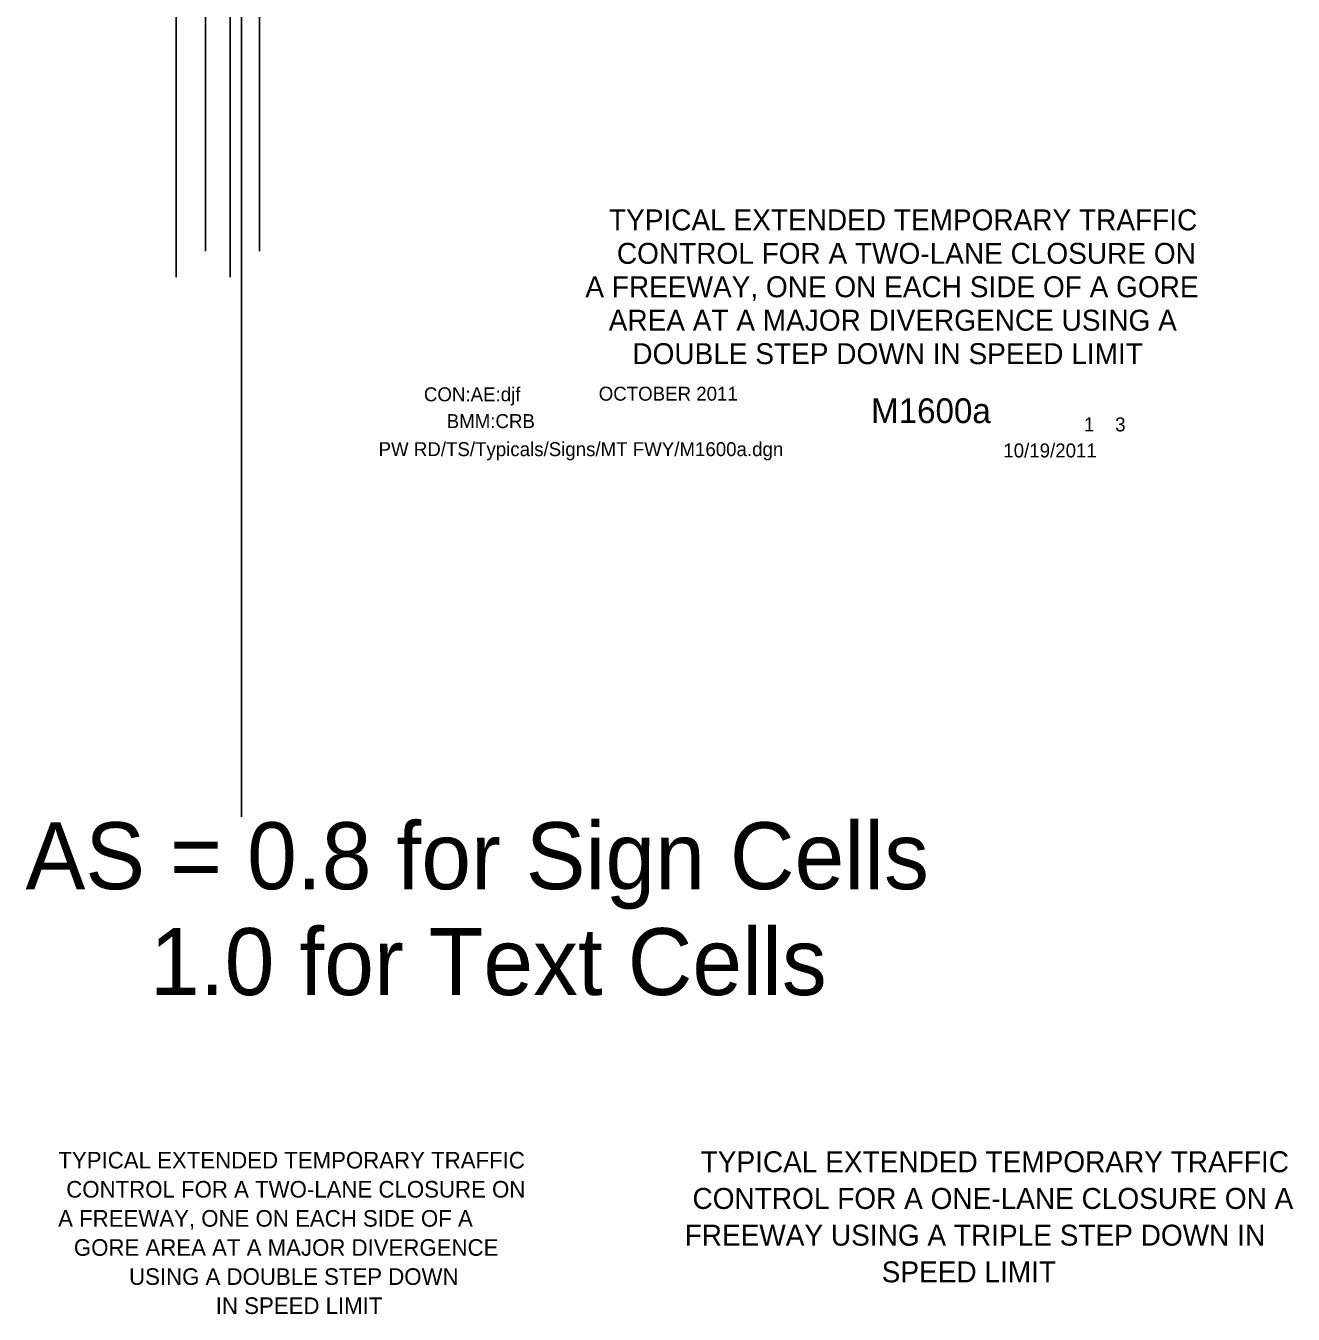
# Model space of a CAD drawing. Extents: x 16728 to 19508, y 5553 to 7079.
# Drawn here: x 16914 to 17477, y 5553 to 6125 of the extents above; entities that cross this region are included whole.
import ezdxf

# ---------------------------------------------------------------- set-up
doc = ezdxf.new("R2010")
doc.units = 0
for name, color, linetype in [('ALI_LEGAL_EX', 7, 'Continuous'), ('BORDER', 7, 'Continuous'), ('BORDER_SIGNAL_WO', 7, 'Continuous')]:
    doc.layers.add(name, color=color, linetype=linetype)

msp = doc.modelspace()

# ---------------------------------------------------------------- linework, layer by layer
at = {"layer": 'ALI_LEGAL_EX'}
for p, q in [((16980.68, 6877.04), (16980.68, 6013.12)), ((17004.68, 6877.04), (17004.68, 6013.12)), ((16993.65, 6024.8), (16993.65, 6525.15)), ((17017.65, 6024.8), (17017.65, 6525.15)), ((17009.75, 5773.57), (17009.75, 6383.76))]:
    msp.add_line(p, q, dxfattribs=at)
msp.add_lwpolyline([(16993.65, 6049.8), (16993.65, 6024.8)], dxfattribs=at)

# ---------------------------------------------------------------- texts
at = {"layer": 'BORDER'}
for s, height, p in [('TYPICAL EXTENDED TEMPORARY TRAFFIC', 9.3, (17172.85, 6033.97)), ('CONTROL FOR A TWO-LANE CLOSURE ON', 9.3, (17176.35, 6019.11)), ('A FREEWAY, ONE ON EACH SIDE OF A GORE', 9.3, (17162.37, 6004.27)), ('AREA AT A MAJOR DIVERGENCE USING A', 9.3, (17172.72, 5989.41)), ('DOUBLE STEP DOWN IN SPEED LIMIT', 9.3, (17183.22, 5974.57)), ('TYPICAL EXTENDED TEMPORARY TRAFFIC', 7.3743, (16928.4, 5617.4)), ('TYPICAL EXTENDED TEMPORARY TRAFFIC', 9.3, (17213.56, 5615.73)), ('CONTROL FOR A TWO-LANE CLOSURE ON', 7.3743, (16931.9, 5604.47)), ('CONTROL FOR A ONE-LANE CLOSURE ON A', 9.3, (17209.93, 5599.43)), ('A FREEWAY, ONE ON EACH SIDE OF A  ', 7.3743, (16928.28, 5591.55)), ('FREEWAY USING A TRIPLE STEP DOWN IN ', 9.3, (17206.43, 5583.13)), ('GORE AREA AT A MAJOR DIVERGENCE ', 7.3743, (16935.28, 5578.62)), ('USING A DOUBLE STEP DOWN ', 7.3743, (16959.78, 5565.7)), ('SPEED LIMIT', 9.3, (17293.93, 5566.83)), ('IN SPEED LIMIT', 7.3743, (16998.28, 5552.78))]:
    msp.add_text(s, height=height, dxfattribs=at).set_placement(p)
at = {"layer": 'BORDER_SIGNAL_WO'}
for s, height, p in [('CON:AE:djf  ', 6.2, (17090.69, 5958.06)), ('    OCTOBER 2011    ', 6.2, (17159.08, 5958.34)), ('    M1600a   ', 11, (17272.86, 5948.38)), ('BMM:CRB   ', 6.2, (17100.81, 5946.17)), (' 1    3 ', 6.2, (17381.45, 5944.7)), ('PW RD/TS/Typicals/Signs/MT FWY/M1600a.dgn      ', 6.2, (17070.55, 5933.71)), ('10/19/2011    ', 6.2, (17347.93, 5933.13)), ('AS = 0.8 for Sign Cells', 29.7271, (16913.84, 5741.4)), ('     1.0 for Text Cells', 29.7271, (16913.84, 5694.4))]:
    msp.add_text(s, height=height, dxfattribs=at).set_placement(p)

doc.saveas('drawing.dxf')
